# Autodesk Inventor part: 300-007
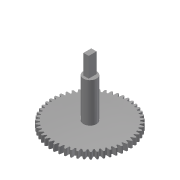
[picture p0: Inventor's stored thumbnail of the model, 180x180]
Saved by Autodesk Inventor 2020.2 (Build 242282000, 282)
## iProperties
Manager: www.cadconsulting.pl
Company: Fabian Stasiak CAD Consulting
CustomPartVersion: 1
Created: 2014-01
Part Number: 300-007
Material: Steel
Document SubType Name: Modeling
Designer: F.Stasiak
Categories: <?xml version="1.0" encoding="UTF-16"?> <MemberInstance><Categories><FamilyTemplate><FamilyTemplateParameter ValueType="xs:double" Id="1" ObjectReferenceKey="da
Density: 1 g/cm^3
Appearance: Steel
Author: F.Stasiak
Subject: Zbiór ćwiczeń. Autodesk Inventor 2020. Kurs podstawowy
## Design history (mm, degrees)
sketch "Sketch1"
  geometry: C1 r 59.067 at (0, 0)
  constraints: 1 centre point
  dimensions: "d0" = 118.13341 diameter of C1 (= da_da)
extrude "Extrusion1" new body sketch "Sketch1" distance "d1" = 10 (= da_b); taper "d2" = 0 deg
workplane "Work Plane2"
sketch "Sketch2"
  geometry: C1 r 59.067 at (0, 0) reference; C2 r 57.465 at (0, 0)
  constraints: 1 centre point, 1 coincident
  dimensions: "d3" = 114.92958 diameter of C2 (= da_dw)
feature "Średnica podziałowa" sketch "Sketch2" dims "d4" = 10, "d5" = 0
workplane "Work Plane8"
workplane "Work Plane9"
feature "Przekładnia walcowa" dims "da_b" = 10, "da_d" = 114.75, "da_aw" = 80, "da_da" = 118.13341, "da_df" = 108.00988, "da_dw" = 114.92958, angle "da_beta" = 0 deg, "da_lefttooth" = 0, "da_righttooth" = 0
sketch "Szkic3"
  geometry: C1 r 10 at (0, 0); A1 r 59.067 centre (0, 0) between (-6.355, 58.724) and (-8.16, 58.5) reference
  constraints: 1 centre point, 1 coincident
  dimensions: "d49" = 20 diameter of C1
extrude "Wyciągnięcie proste2" join sketch "Szkic3" distance "d50" = 60; taper "d51" = 0 deg
sketch "Szkic4"
  geometry: L1 (4, 6)-(-4, 6); L2 (-4, 6)-(-4, -6); L3 (-4, -6)-(4, -6); L4 (4, -6)-(4, 6); L5 (4, 6)-(-4, -6); L6 (-4, 6)-(4, -6); 1 further point
  constraints: 12 end point, 2 midpoint, 2 parallel, 1 horizontal, 1 perpendicular
  dimensions: "d54" = 8 distance of L3.end L2.end; "d55" = 12 distance of L2.end L1.end
extrude "Wyciągnięcie proste3" join sketch "Szkic4" distance "d52" = 30; taper "d53" = 0 deg
body "Solid1"
body "Srf1"
other parameters: "d17" = 0, "d34" = 0.616 (computed from da_z), "d39" = 0, "d41" = 0, "d47" = 0, "d48" = 0
